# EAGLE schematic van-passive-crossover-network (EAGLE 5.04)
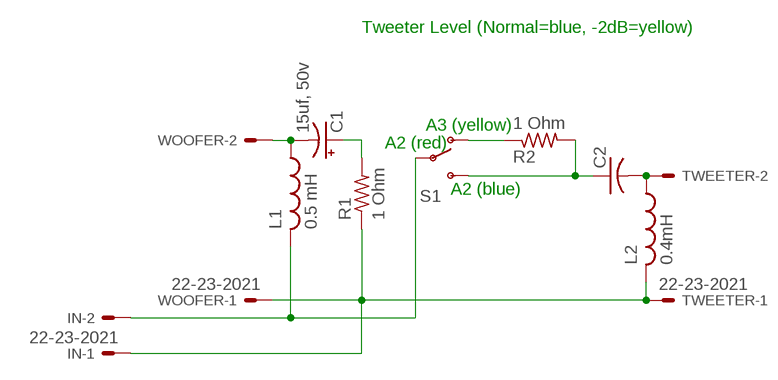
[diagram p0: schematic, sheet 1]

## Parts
C1  15uf, 50v  CPOL-US153CLV-0605  [153CLV-0605]
C2  C-US150-091X182  [C150-091X182]
IN  22-23-2021  [22-23-2021]
L1  0.5 mH  L-USPIS2816  [PIS2816]
L2  0.4mH  L-USPIS2816  [PIS2816]
R1  1 Ohm  R-US_V234/12  [V234/12]
R2  1 Ohm  R-US_V234/12  [V234/12]
S1  SWITCH-SPSTPTH  [SWITCH-SPDT]
TWEETER  22-23-2021  [22-23-2021]
WOOFER  22-23-2021  [22-23-2021]

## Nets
N$1: IN.1 L2.2 R1.1 TWEETER.1 WOOFER.1
N$3: IN.2 L1.2 S1.2(P)
N$4: R2.1 S1.1(O)
N$5: C2.1 R2.2 S1.3(S)
N$6: C1.+ R1.2
N$7: C1.- L1.1 WOOFER.2
N$8: C2.2 L2.1 TWEETER.2

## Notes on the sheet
- Tweeter Level (Normal=blue, -2dB=yellow)
- A3 (yellow)
- A2 (red)
- A2 (blue)

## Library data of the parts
C1 = resistor:CPOL-US: POLARIZED CAPACITOR, American symbol
C2 = resistor:C-US: CAPACITOR, American symbol
IN TWEETER WOOFER = con-molex:22-23-2021: .100" (2.54mm) Center Header - 2 Pin
L1 L2 = rcl:L-US: INDUCTOR, American symbol
R1 R2 = rcl:R-US_: RESISTOR, American symbol
S1 = SparkFun:SWITCH-SPST: SPST Switch Simple slide switch. Spark Fun Electronics SKU : COM-00102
